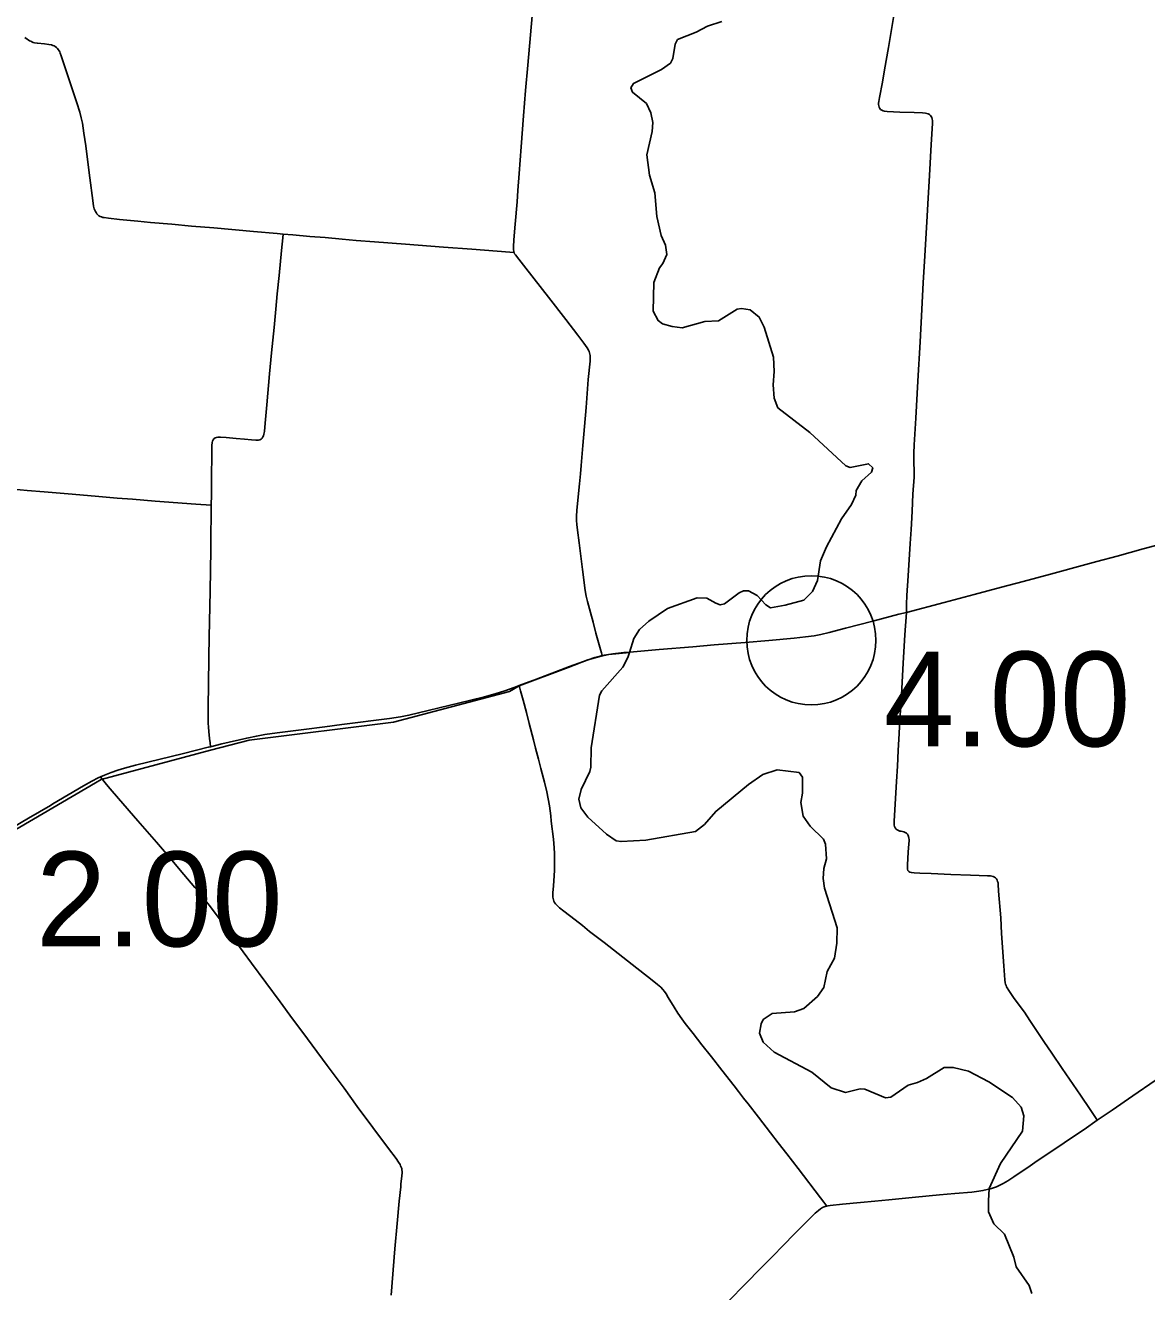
# Model space of a CAD drawing. Extents: x 1597222 to 1925846, y 496284 to 911751.
# Drawn here: x 1674019 to 1687037, y 546977 to 561679 of the extents above; entities that cross this region are included whole.
import ezdxf

# ---------------------------------------------------------------- set-up
doc = ezdxf.new("R2010")
doc.units = 0
for name, color, linetype in [('Default', 7, 'Continuous'), ('GM_X_County_Road', 7, 'Continuous'), ('GM_X_Township', 7, 'Continuous'), ('GM_X_Township_Road', 7, 'Continuous'), ('GM_X_US_Route', 7, 'Continuous')]:
    doc.layers.add(name, color=color, linetype=linetype)

msp = doc.modelspace()

# ---------------------------------------------------------------- linework, layer by layer
at = {"layer": 'Default'}
msp.add_circle((1683144, 554539), 750, dxfattribs=at)
msp.add_circle((1683144, 554539), 750, dxfattribs=at)
at = {"layer": 'GM_X_County_Road'}
for points in [[(1679693, 559040), (1679692, 559042), (1679689, 559058), (1679687, 559074), (1679686, 559107), (1679692, 559189), (1679707, 559369), (1679727, 559631), (1679737, 559762), (1679752, 559958), (1679776, 560269), (1679803, 560629), (1679826, 560923), (1679853, 561217), (1679916, 561920)], [(1674013, 561539), (1674039, 561518), (1674052, 561509), (1674066, 561500), (1674081, 561493), (1674096, 561487), (1674111, 561481), (1674127, 561477), (1674160, 561471), (1674241, 561464), (1674290, 561457), (1674322, 561451), (1674338, 561446), (1674353, 561440), (1674367, 561432), (1674380, 561422), (1674392, 561410), (1674402, 561398), (1674411, 561384), (1674419, 561370), (1674425, 561354), (1674437, 561324), (1674523, 561058), (1674617, 560778), (1674652, 560669), (1674669, 560605), (1674682, 560541), (1674700, 560428), (1674720, 560281), (1674736, 560151), (1674769, 559907), (1674803, 559647), (1674812, 559581), (1674820, 559550), (1674826, 559534), (1674832, 559519), (1674840, 559505), (1674850, 559492), (1674861, 559480), (1674873, 559469), (1674887, 559461), (1674902, 559454), (1674918, 559449), (1674934, 559446), (1674983, 559440), (1675113, 559425), (1675326, 559404), (1675473, 559391), (1675718, 559370), (1675947, 559349), (1676208, 559326), (1676666, 559286), (1676944, 559262), (1677011, 559256)], [(1677011, 559256), (1677124, 559245), (1677320, 559229), (1677500, 559214), (1677696, 559196), (1677859, 559180), (1678072, 559165), (1678432, 559138), (1678874, 559105), (1679201, 559080), (1679496, 559058), (1679643, 559044), (1679693, 559040)], [(1680555, 557569), (1680576, 557780), (1680578, 557813), (1680577, 557846), (1680574, 557862), (1680570, 557878), (1680564, 557893), (1680557, 557908), (1680541, 557936), (1680503, 557990), (1680434, 558082), (1680294, 558264), (1680094, 558524), (1679831, 558860), (1679749, 558963), (1679708, 559014), (1679698, 559027), (1679693, 559040)], [(1680716, 554362), (1680707, 554392), (1680695, 554434), (1680643, 554623), (1680610, 554750), (1680579, 554861), (1680545, 554988), (1680530, 555051), (1680519, 555116), (1680486, 555360), (1680447, 555670), (1680428, 555817), (1680422, 555882), (1680419, 555931), (1680418, 555981), (1680422, 556046), (1680430, 556128), (1680453, 556357), (1680464, 556471), (1680472, 556570), (1680492, 556799), (1680528, 557241), (1680555, 557569)], [(1680035, 552935), (1680005, 553050), (1679977, 553161), (1679943, 553288), (1679919, 553383), (1679870, 553573), (1679836, 553700), (1679798, 553843), (1679768, 553953), (1679764, 553969), (1679753, 554014)], [(1680118, 552502), (1680103, 552619), (1680090, 552700), (1680074, 552780), (1680047, 552891), (1680035, 552935)], [(1680486, 551228), (1680401, 551293), (1680337, 551343), (1680272, 551394), (1680221, 551435), (1680196, 551457), (1680184, 551468), (1680173, 551481), (1680163, 551495), (1680155, 551510), (1680149, 551526), (1680145, 551542), (1680142, 551559), (1680142, 551576), (1680143, 551609), (1680151, 551690), (1680159, 551805), (1680161, 551870), (1680162, 552066), (1680160, 552131), (1680151, 552229), (1680125, 552440), (1680118, 552502)], [(1683322, 547972), (1683289, 548015), (1683250, 548068), (1682991, 548407), (1682861, 548576), (1682760, 548706), (1682670, 548823), (1682530, 549005), (1682409, 549160), (1682358, 549225), (1682298, 549303), (1682248, 549368), (1682105, 549548), (1681985, 549704), (1681872, 549845), (1681771, 549974), (1681679, 550091), (1681640, 550144), (1681594, 550212), (1681550, 550281), (1681483, 550394), (1681458, 550436), (1681439, 550462), (1681418, 550487), (1681396, 550511), (1681359, 550544), (1681295, 550595), (1681063, 550777), (1680739, 551030), (1680570, 551160), (1680486, 551228)], [(1686464, 548967), (1686635, 549084), (1686878, 549251), (1687135, 549428), (1687378, 549596), (1687650, 549782)], [(1685208, 548169), (1685248, 548180), (1685295, 548196), (1685326, 548209), (1685370, 548232), (1685426, 548265), (1685495, 548310), (1685685, 548440), (1685766, 548495), (1685902, 548587), (1686078, 548707), (1686187, 548780), (1686310, 548862), (1686464, 548967)], [(1683322, 547972), (1683338, 547975), (1683361, 547978), (1683505, 547993), (1683716, 548013), (1683880, 548027), (1684043, 548043), (1684353, 548073), (1684631, 548100), (1684810, 548116), (1685006, 548133), (1685088, 548144), (1685136, 548152), (1685185, 548163), (1685208, 548169)], [(1681373, 546046), (1681485, 546161), (1681647, 546324), (1681854, 546534), (1681969, 546651), (1682165, 546850), (1682394, 547084), (1682544, 547236), (1682671, 547364), (1682843, 547540), (1682923, 547622), (1683085, 547785), (1683190, 547889), (1683226, 547921), (1683252, 547941), (1683272, 547953), (1683291, 547962), (1683306, 547968), (1683322, 547972)]]:
    msp.add_lwpolyline(points, dxfattribs=at)
at = {"layer": 'GM_X_Township'}
for points in [[(1682105, 561724), (1681940, 561668), (1681808, 561598), (1681591, 561514), (1681563, 561460), (1681535, 561292), (1681508, 561240), (1681406, 561167), (1681078, 561005), (1681050, 560953), (1681068, 560901), (1681231, 560771), (1681281, 560664), (1681303, 560552), (1681295, 560448), (1681233, 560177), (1681265, 559940), (1681327, 559734), (1681349, 559461), (1681401, 559237), (1681449, 559126), (1681465, 559020), (1681421, 558914), (1681381, 558862), (1681314, 558693), (1681306, 558361), (1681366, 558252), (1681417, 558214), (1681527, 558182), (1681644, 558168), (1681907, 558242), (1682066, 558250), (1682281, 558382), (1682335, 558390), (1682435, 558374), (1682540, 558292), (1682596, 558173), (1682704, 557828), (1682714, 557660), (1682700, 557506), (1682712, 557349), (1682754, 557239), (1683128, 556952), (1683545, 556565), (1683596, 556547), (1683807, 556589), (1683857, 556543), (1683841, 556490), (1683732, 556390), (1683664, 556280), (1683660, 556226), (1683611, 556116), (1683493, 555951), (1683320, 555625), (1683250, 555462), (1683215, 555232), (1683157, 555105), (1683057, 555005), (1682842, 554949), (1682671, 554917), (1682617, 554951), (1682516, 555058), (1682416, 555114), (1682358, 555114), (1682305, 555090), (1682136, 554964), (1682086, 554950), (1682036, 554970), (1681932, 555030), (1681817, 555032), (1681474, 554908), (1681259, 554760), (1681150, 554664), (1681084, 554559), (1681033, 554399), (1680792, 554374), (1680704, 554356), (1680548, 554311), (1680321, 554225), (1679753, 554009), (1679638, 553946), (1678293, 553590), (1676617, 553380), (1676167, 553264), (1674900, 552924), (1674834, 552885), (1672464, 551499)], [(1681033, 554399), (1681013, 554339), (1680955, 554227), (1680712, 553952), (1680684, 553902), (1680587, 553291), (1680583, 553066), (1680573, 553016), (1680472, 552808), (1680446, 552697), (1680468, 552593), (1680548, 552485), (1680767, 552288), (1680880, 552212), (1680936, 552202), (1681223, 552220), (1681798, 552320), (1681902, 552400), (1682035, 552552), (1682415, 552864), (1682582, 552981), (1682746, 553037), (1683001, 553006), (1683040, 552950), (1683040, 552766), (1683021, 552658), (1683049, 552497), (1683130, 552383), (1683284, 552232), (1683310, 552174), (1683320, 552002), (1683290, 551890), (1683282, 551775), (1683296, 551661), (1683445, 551200), (1683441, 551023), (1683412, 550851), (1683326, 550693), (1683288, 550510), (1683215, 550406), (1683055, 550266), (1682948, 550228), (1682689, 550206), (1682584, 550136), (1682560, 550086), (1682542, 549977), (1682586, 549873), (1682713, 549759), (1683151, 549526), (1683374, 549343), (1683542, 549291), (1683709, 549331), (1683763, 549329), (1684004, 549229), (1684065, 549235), (1684269, 549373), (1684376, 549405), (1684480, 549451), (1684685, 549579), (1684792, 549581), (1684969, 549539), (1685206, 549414), (1685479, 549230), (1685581, 549121), (1685611, 549017), (1685595, 548841), (1685340, 548466), (1685207, 548175), (1685201, 548033), (1685202, 547903), (1685263, 547764), (1685385, 547644), (1685494, 547380), (1685523, 547264), (1685671, 547050), (1685704, 546958)]]:
    msp.add_lwpolyline(points, dxfattribs=at)
at = {"layer": 'GM_X_Township_Road'}
for points in [[(1684247, 554864), (1684248, 554908), (1684249, 554959), (1684252, 555058), (1684268, 555287), (1684292, 555663), (1684302, 555827), (1684306, 555892), (1684313, 556039), (1684324, 556236), (1684336, 556432), (1684338, 556481), (1684334, 556629), (1684335, 556711), (1684339, 556809), (1684357, 557120), (1684380, 557546), (1684406, 558004), (1684427, 558381), (1684444, 558692), (1684457, 558937), (1684483, 559396), (1684499, 559674), (1684516, 559936), (1684535, 560296), (1684548, 560476), (1684552, 560542), (1684551, 560575), (1684548, 560591), (1684543, 560607), (1684536, 560621), (1684526, 560633), (1684514, 560643), (1684500, 560651), (1684484, 560656), (1684468, 560660), (1684435, 560663), (1684337, 560667), (1684173, 560672), (1684025, 560678), (1683992, 560682), (1683976, 560686), (1683961, 560693), (1683948, 560702), (1683938, 560713), (1683930, 560728), (1683926, 560743), (1683924, 560760), (1683924, 560776), (1683926, 560793), (1683936, 560841), (1683969, 561018), (1683995, 561164), (1684041, 561422), (1684122, 561907)], [(1676177, 556108), (1676180, 556229), (1676182, 556425), (1676186, 556703), (1676186, 556802), (1676189, 556834), (1676193, 556850), (1676199, 556865), (1676209, 556878), (1676222, 556888), (1676237, 556894), (1676253, 556897), (1676286, 556897), (1676352, 556893), (1676466, 556884), (1676564, 556874), (1676645, 556866), (1676694, 556861), (1676711, 556861), (1676727, 556863), (1676742, 556868), (1676756, 556876), (1676768, 556887), (1676777, 556900), (1676784, 556915), (1676788, 556931), (1676794, 556964), (1676803, 557061), (1676822, 557274), (1676855, 557632), (1676877, 557877), (1676906, 558170), (1676927, 558382), (1676943, 558561), (1676964, 558773), (1676993, 559066), (1677007, 559213), (1677011, 559256)], [(1673766, 556266), (1673771, 556280), (1673780, 556290), (1673796, 556293), (1673828, 556296), (1673861, 556294), (1673960, 556286), (1674042, 556279), (1674237, 556263), (1674563, 556235), (1674873, 556210), (1675085, 556191), (1675264, 556176), (1675525, 556156), (1675998, 556120), (1676177, 556108)], [(1676170, 553304), (1676165, 553351), (1676159, 553400), (1676150, 553481), (1676146, 553530), (1676143, 553578), (1676141, 553676), (1676141, 553775), (1676144, 554020), (1676149, 554347), (1676153, 554576), (1676163, 555115), (1676171, 555590), (1676173, 555802), (1676176, 555950), (1676177, 556108)], [(1686464, 548967), (1686443, 548999), (1686379, 549094), (1686269, 549257), (1686057, 549569), (1685937, 549745), (1685844, 549880), (1685681, 550126), (1685617, 550221), (1685569, 550288), (1685492, 550394), (1685436, 550475), (1685419, 550503), (1685411, 550517), (1685405, 550532), (1685399, 550548), (1685396, 550563), (1685391, 550596), (1685379, 550759), (1685353, 551136), (1685343, 551316), (1685318, 551626), (1685313, 551709), (1685311, 551725), (1685307, 551741), (1685301, 551756), (1685293, 551770), (1685282, 551782), (1685269, 551791), (1685254, 551797), (1685238, 551801), (1685222, 551804), (1685189, 551806), (1685091, 551808), (1684992, 551812), (1684763, 551821), (1684534, 551831), (1684403, 551836), (1684337, 551839), (1684305, 551843), (1684289, 551848), (1684274, 551856), (1684264, 551868), (1684260, 551884), (1684261, 551933), (1684269, 552080), (1684275, 552178), (1684278, 552211), (1684278, 552228), (1684277, 552244), (1684273, 552260), (1684267, 552275), (1684259, 552289), (1684247, 552300), (1684234, 552310), (1684218, 552316), (1684202, 552319), (1684186, 552322), (1684170, 552325), (1684155, 552330), (1684140, 552338), (1684128, 552348), (1684118, 552361), (1684111, 552376), (1684107, 552392), (1684105, 552408), (1684105, 552441), (1684134, 552899), (1684143, 553079), (1684153, 553259), (1684165, 553456), (1684173, 553619), (1684186, 553832), (1684195, 553980), (1684211, 554274), (1684228, 554602), (1684247, 554864)], [(1678267, 546935), (1678310, 547475), (1678335, 547769), (1678359, 548030), (1678377, 548193), (1678380, 548226), (1678391, 548324), (1678394, 548357), (1678393, 548374), (1678391, 548391), (1678388, 548407), (1678382, 548423), (1678376, 548438), (1678369, 548453), (1678351, 548482), (1678323, 548522), (1678234, 548640), (1677873, 549128), (1677720, 549341), (1677523, 549603), (1677348, 549841), (1677240, 549986), (1677122, 550144), (1676977, 550342), (1676646, 550791), (1676452, 551055), (1676292, 551278), (1676203, 551397), (1676153, 551464), (1676108, 551522), (1676063, 551579), (1676032, 551619), (1675988, 551671), (1675860, 551820), (1675680, 552033), (1675542, 552195), (1675327, 552444), (1675102, 552704), (1675004, 552815), (1674961, 552864), (1674931, 552903), (1674891, 552953)]]:
    msp.add_lwpolyline(points, dxfattribs=at)
at = {"layer": 'GM_X_US_Route'}
msp.add_lwpolyline([(1673760, 552299), (1674057, 552474), (1674312, 552623), (1674340, 552640), (1674693, 552848), (1674793, 552904), (1674866, 552942), (1674891, 552953), (1674940, 552975), (1675016, 553006), (1675093, 553032), (1675172, 553056), (1675298, 553090), (1675856, 553227), (1676143, 553297), (1676170, 553304), (1676302, 553337), (1676589, 553404), (1676701, 553428), (1676798, 553445), (1676944, 553466), (1677253, 553505), (1677497, 553536), (1677692, 553560), (1678245, 553631), (1678375, 553652), (1678472, 553670), (1678584, 553696), (1678935, 553781), (1679174, 553840), (1679348, 553885), (1679475, 553919), (1679585, 553954), (1679693, 553992), (1679753, 554014), (1679954, 554090), (1680338, 554235), (1680554, 554313), (1680631, 554339), (1680694, 554357), (1680716, 554362), (1680742, 554368), (1680790, 554376), (1680839, 554383), (1680969, 554396), (1681035, 554402), (1681378, 554432), (1681770, 554463), (1682015, 554485), (1682374, 554515), (1682652, 554539), (1682946, 554565), (1683077, 554579), (1683175, 554593), (1683255, 554608), (1683352, 554630), (1683542, 554680), (1683859, 554762), (1684161, 554841), (1684247, 554864), (1684684, 554980), (1685033, 555071), (1685350, 555155), (1685604, 555222), (1685920, 555309), (1686332, 555420), (1686459, 555453), (1686696, 555518), (1686997, 555600), (1687377, 555703)], dxfattribs=at)

# ---------------------------------------------------------------- texts
at = {"layer": 'Default'}
for s, p in [('4.00', (1683986, 553308)), ('4.00', (1683986, 553308)), ('2.00', (1674143, 550986)), ('2.00', (1674143, 550986))]:
    msp.add_text(s, height=1100, dxfattribs=at).set_placement(p)

doc.saveas('drawing.dxf')
